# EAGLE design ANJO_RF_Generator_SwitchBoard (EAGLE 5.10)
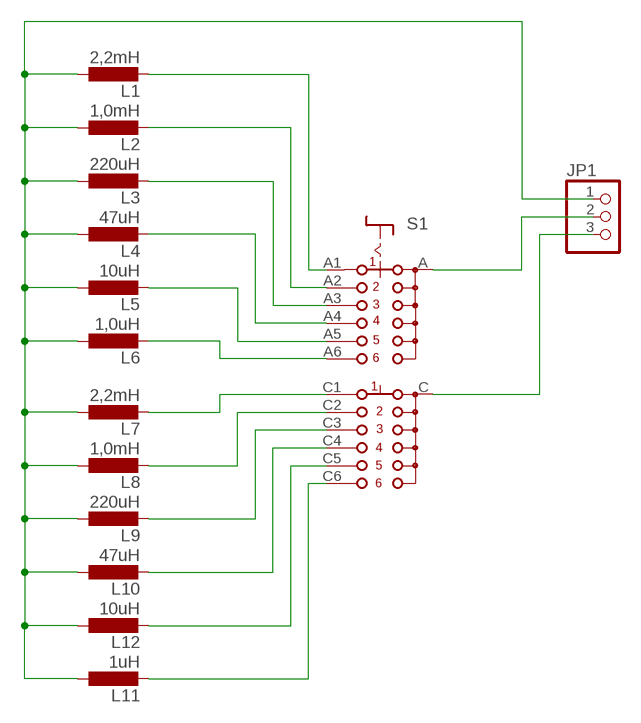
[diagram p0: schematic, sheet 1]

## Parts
JP1  PINHD-1X3  [1X03]
L1  2,2mH  L-EU0207/10  [0207/10]
L2  1,0mH  L-EU0207/10  [0207/10]
L3  220uH  L-EU0207/10  [0207/10]
L4  47uH  L-EU0207/10  [0207/10]
L5  10uH  L-EU0207/10  [0207/10]
L6  1,0uH  L-EU0207/10  [0207/10]
L7  2,2mH  L-EU0207/10  [0207/10]
L8  1,0mH  L-EU0207/10  [0207/10]
L9  220uH  L-EU0207/10  [0207/10]
L10  47uH  L-EU0207/10  [0207/10]
L11  1uH  L-EU0207/10  [0207/10]
L12  10uH  L-EU0207/10  [0207/10]
S1  CK102X06  [CK102X06]

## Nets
N$1: L1.2 S1.A1
N$2: L2.2 S1.A2
N$3: L3.2 S1.A3
N$4: L4.2 S1.A4
N$5: L5.2 S1.A5
N$6: L6.2 S1.A6
N$7: L7.2 S1.C1
N$8: L8.2 S1.C2
N$9: L9.2 S1.C3
N$10: L10.2 S1.C4
N$11: L12.2 S1.C5
N$12: L11.2 S1.C6
N$13: JP1.1 L1.1 L2.1 L3.1 L4.1 L5.1 L6.1 L7.1 L8.1 L9.1 L10.1 L11.1 L12.1
N$14: JP1.3 S1.C
N$15: JP1.2 S1.A

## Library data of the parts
JP1 = pinhead:PINHD-1X3: PIN HEADER
L1-L12 = resistor:L-EU: INDUCTOR, European symbol
S1 = switch:CK102X06: ROTARY SWITCH C&K

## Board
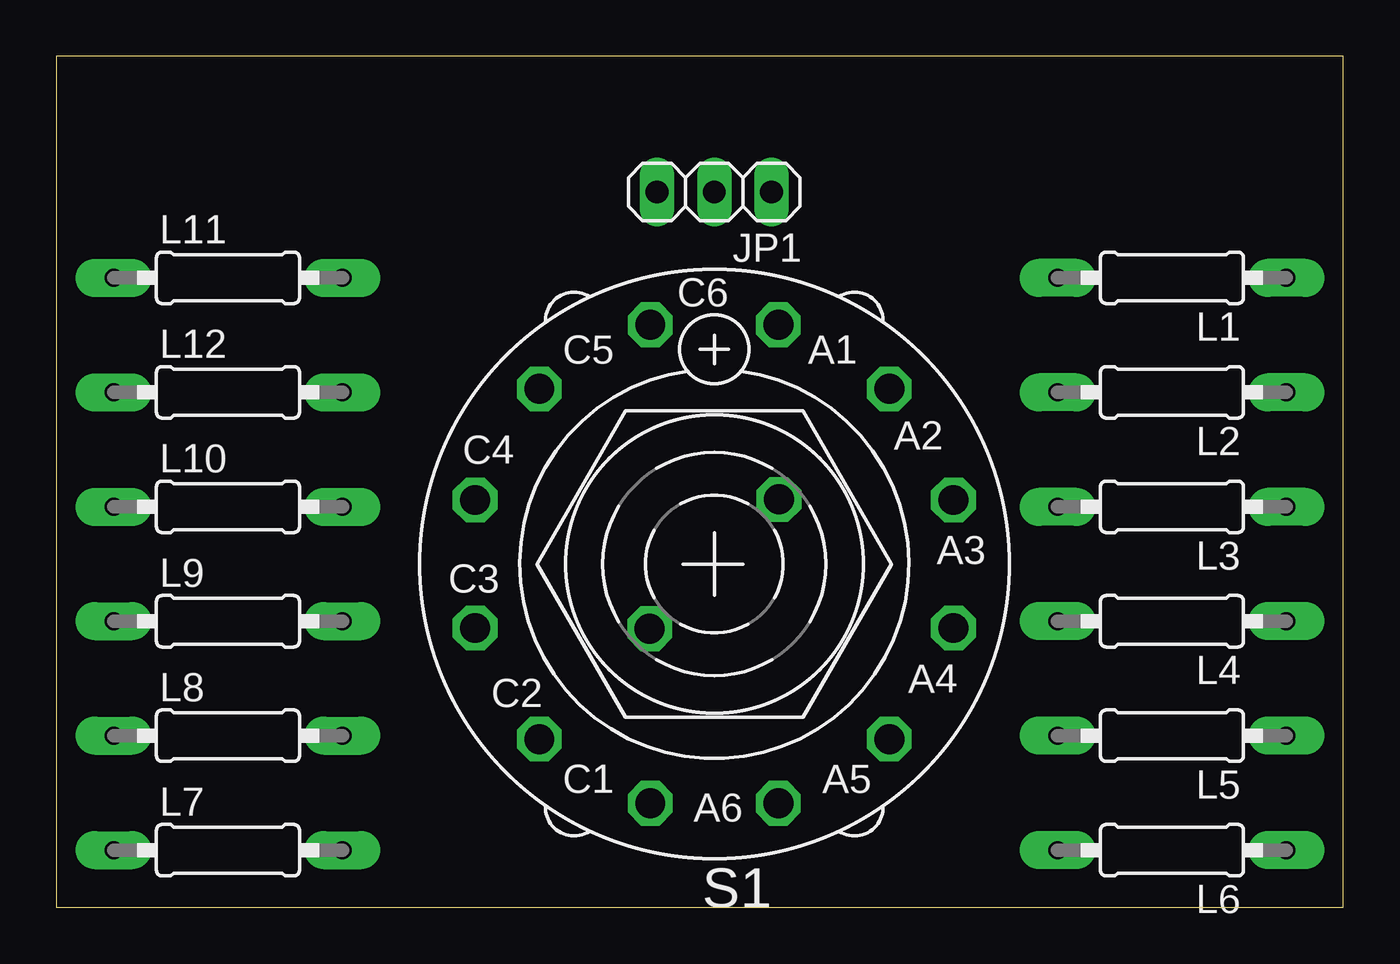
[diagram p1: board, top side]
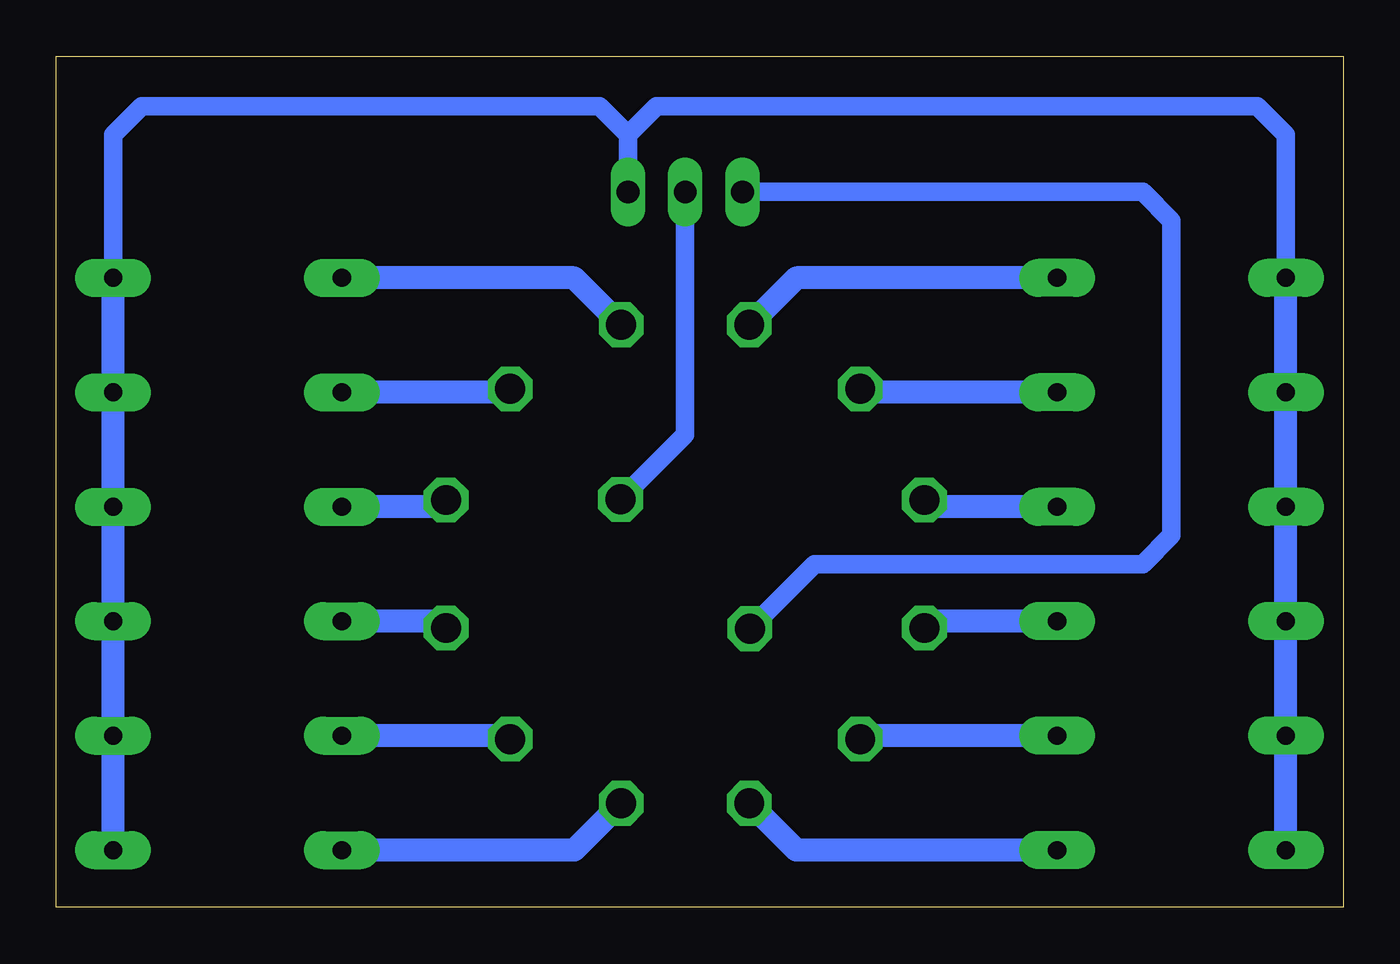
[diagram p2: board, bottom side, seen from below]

Size 57.13 x 37.77 mm. Coordinates in mm from the lower left corner, seen from the top.
Outline: 0,0 57.13,0 57.13,37.77 0,37.77 0,0
Copper layers (1*16): Top 0.035mm / dielectric 1.5mm / Bottom 0.035mm
Design rules "default": minimum track width 10mil, minimum drill 24mil, track to track 8mil, track to pad 8mil, pad to pad 8mil, via to via 8mil, smd to smd 8mil, copper to edge 40mil, drill to drill 8mil, minimum pad ring 10mil, minimum via ring 8mil, stop-mask expansion 4mil, vias tented up to drill 0mil, thermal gap 10mil

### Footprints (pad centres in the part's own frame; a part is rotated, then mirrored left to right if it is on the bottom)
1X03 = drill 1.016 long: 1 -2.54,0; 2 0,0; 3 2.54,0
0207/10 = drill 0.8 pad 1.676 long: 1 -5.08,0 | drill 0.813 pad 1.676 long: 2 5.08,0
CK102X06 = drill 1.321 octagon: A -2.87,-2.87; A1 -2.845,-10.617; A2 -7.772,-7.772; A3 -10.617,-2.845; A4 -10.617,2.845; A5 -7.772,7.772; A6 -2.845,10.617; C 2.87,2.87; C1 2.845,10.617; C2 7.772,7.772; C3 10.617,2.845; C4 10.617,-2.845; C5 7.772,-7.772; C6 2.845,-10.617

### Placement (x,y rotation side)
JP1  29.21,31.75 180 top
L1  49.53,27.94 180 top
L2  49.53,22.86 180 top
L3  49.53,17.78 180 top
L4  49.53,12.7 180 top
L5  49.53,7.62 180 top
L6  49.53,2.54 180 top
L7  7.62,2.54 0 top
L8  7.62,7.62 0 top
L9  7.62,12.7 0 top
L10  7.62,17.78 0 top
L11  7.62,27.94 0 top
L12  7.62,22.86 0 top
S1  29.21,15.24 180 top

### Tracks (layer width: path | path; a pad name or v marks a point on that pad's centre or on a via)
N$1
  Bottom 1.016: L1.2 34.14,27.94 S1.A1
N$2
  Bottom 1.016: L2.2 37.13,22.86 S1.A2
N$3
  Bottom 1.016: L3.2 40.13,17.78 S1.A3
N$4
  Bottom 1.016: L4.2 40.13,12.7 S1.A4
N$5
  Bottom 1.016: L5.2 37.13,7.62 S1.A5
N$6
  Bottom 1.016: L6.2 34.14,2.54 S1.A6
N$7
  Bottom 1.016: L7.2 24.28,2.54 S1.C1
N$8
  Bottom 1.016: L8.2 21.29,7.62 S1.C2
N$9
  Bottom 1.016: L9.2 18.29,12.7 S1.C3
N$10
  Bottom 1.016: L10.2 18.29,17.78 S1.C4
N$11
  Bottom 1.016: L12.2 21.29,22.86 S1.C5
N$12
  Bottom 1.016: L11.2 24.28,27.94 S1.C6
N$13
  Bottom 0.813: L11.1 2.54,34.29 3.81,35.56 30.48,35.56 31.75,34.29 | JP1.1 31.75,34.29 | 31.75,34.29 33.02,35.56 53.34,35.56 54.61,34.29 L1.1
  Bottom 1.016: L7.1 L8.1 L9.1 L10.1 L12.1 L11.1 | L6.1 L5.1 L4.1 L3.1 L2.1 L1.1
N$14
  Bottom 0.813: JP1.3 8.89,31.75 7.62,30.48 7.62,16.51 8.89,15.24 23.47,15.24 S1.C
N$15
  Bottom 0.813: JP1.2 29.21,20.98 S1.A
